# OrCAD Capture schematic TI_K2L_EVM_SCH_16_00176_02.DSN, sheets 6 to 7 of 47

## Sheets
6 PAGE24 : K2L_JTAG: size C; title: K2L EMU, K2L JTAG, EMU MIPI 60,  EMU Detect, AMC/XDS200
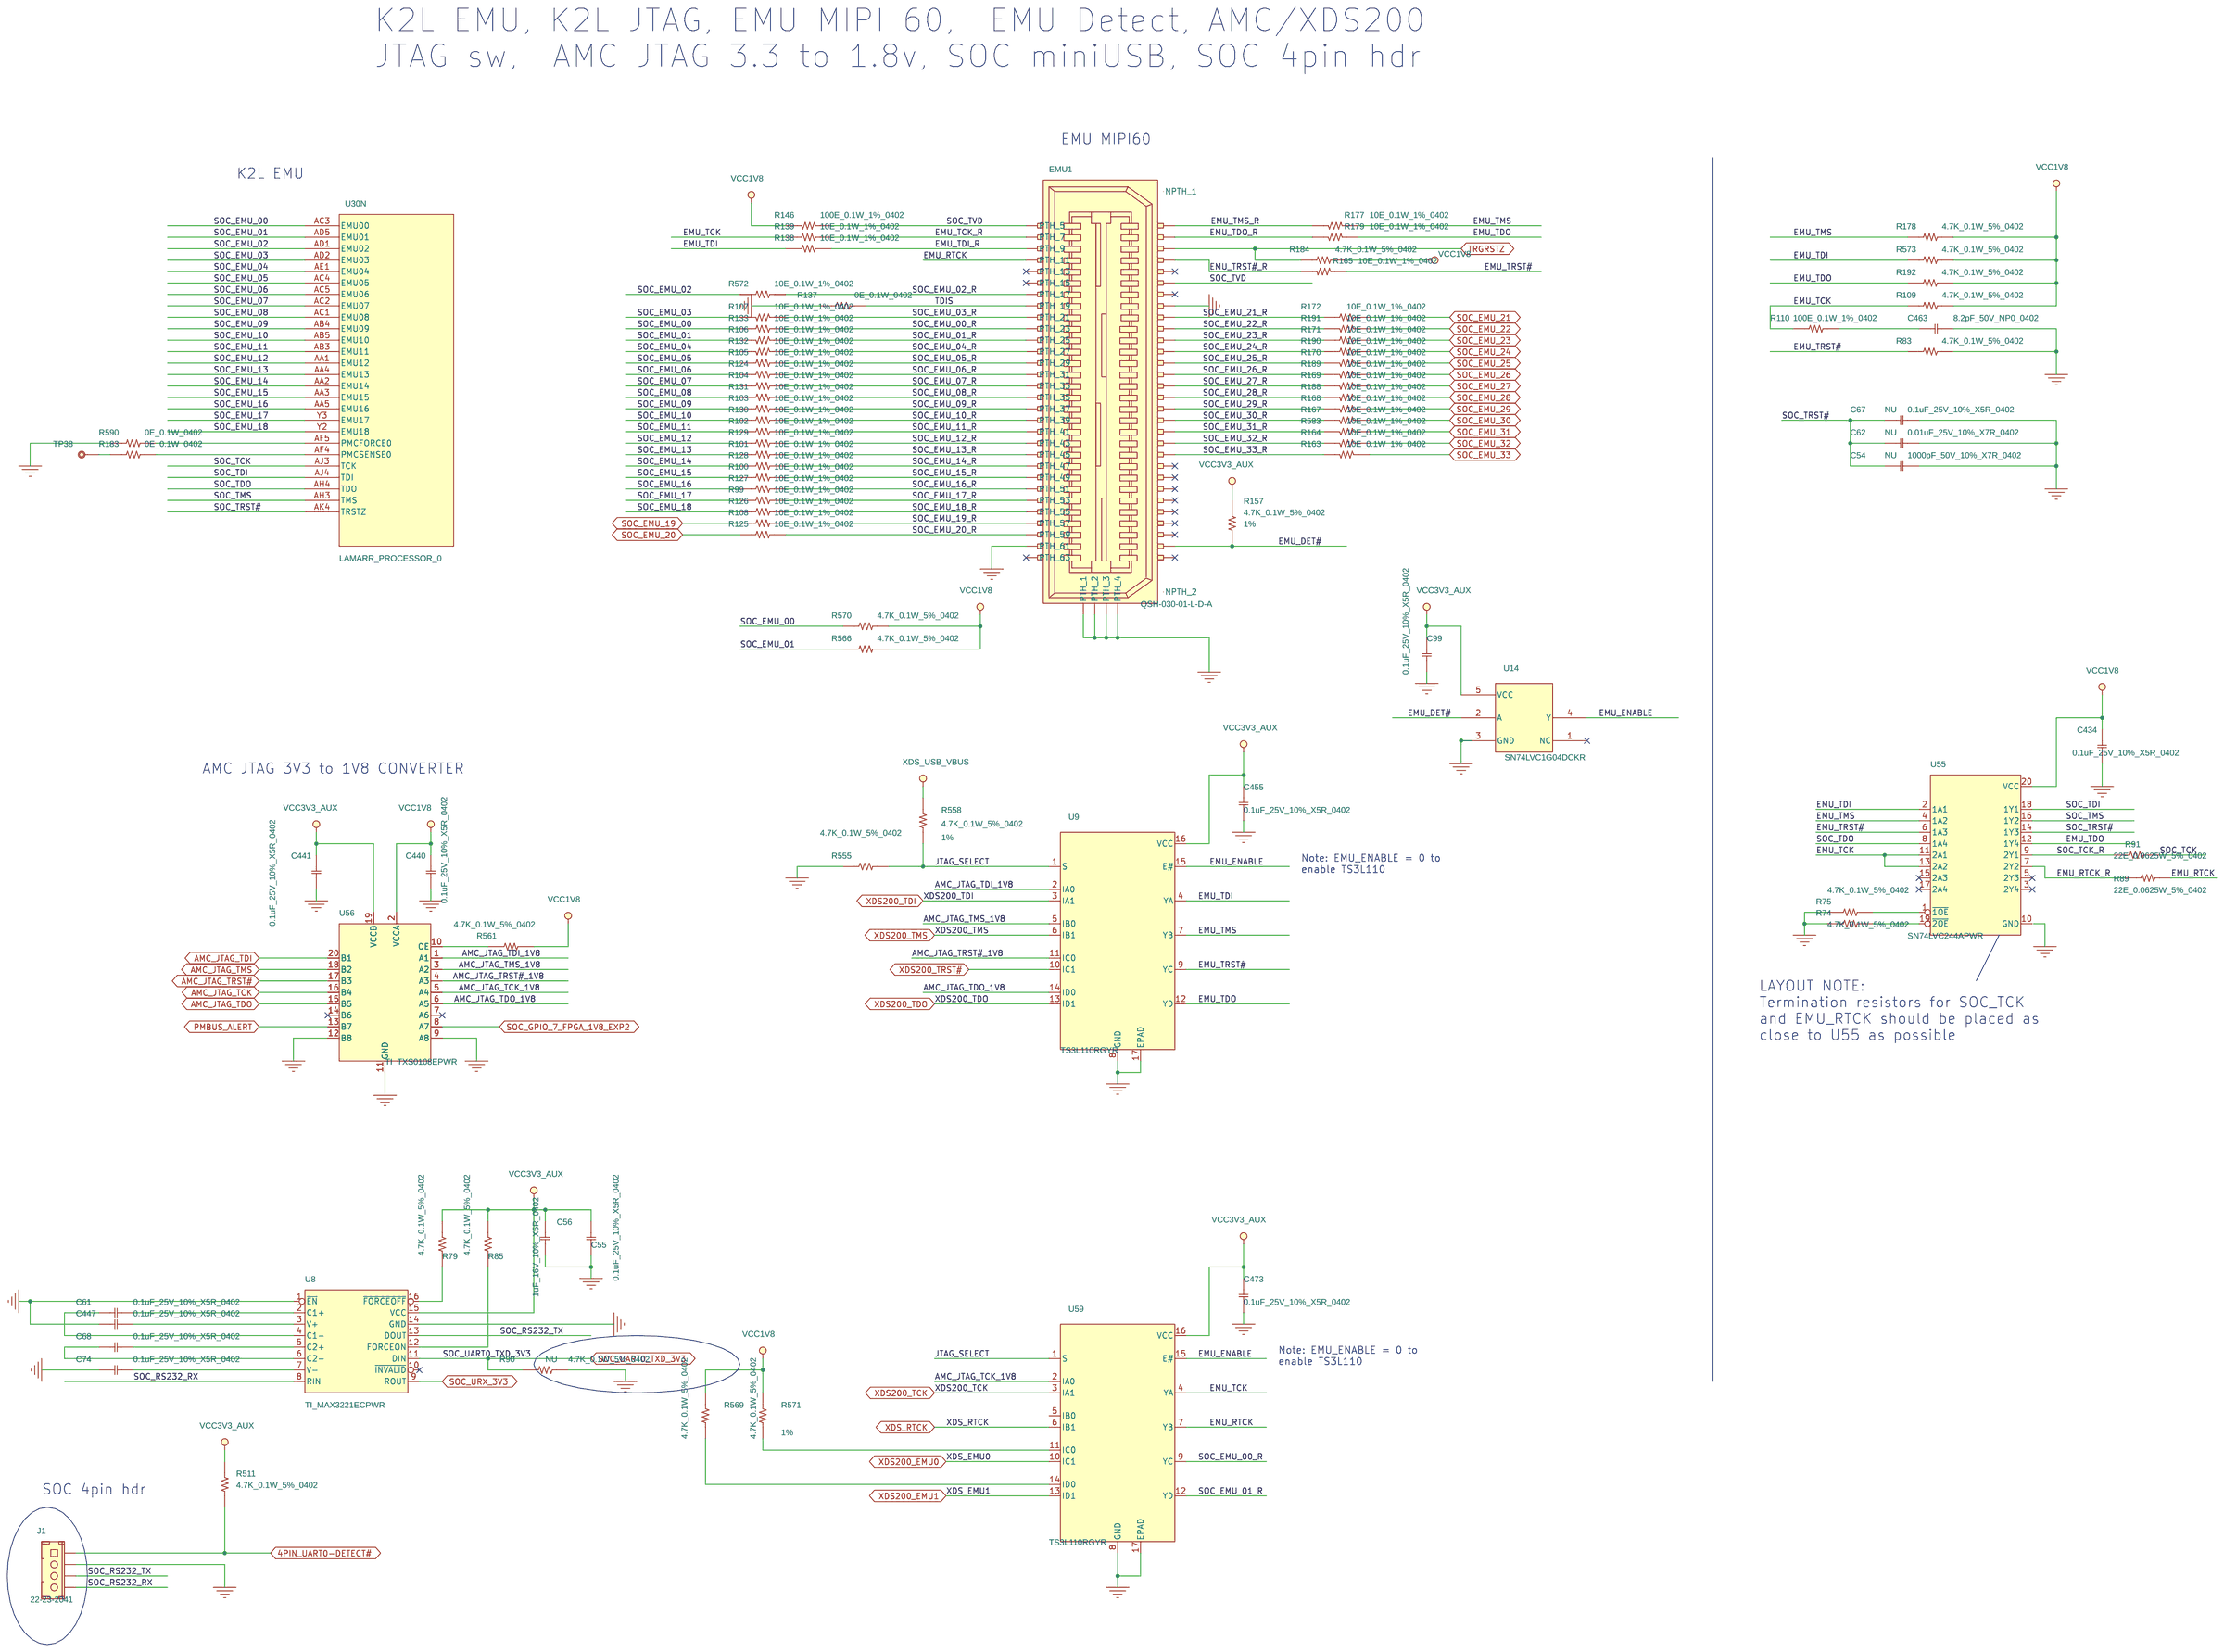
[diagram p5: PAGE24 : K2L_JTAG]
7 PAGE04 : PLACEMENT_C: title: PLACEMENT
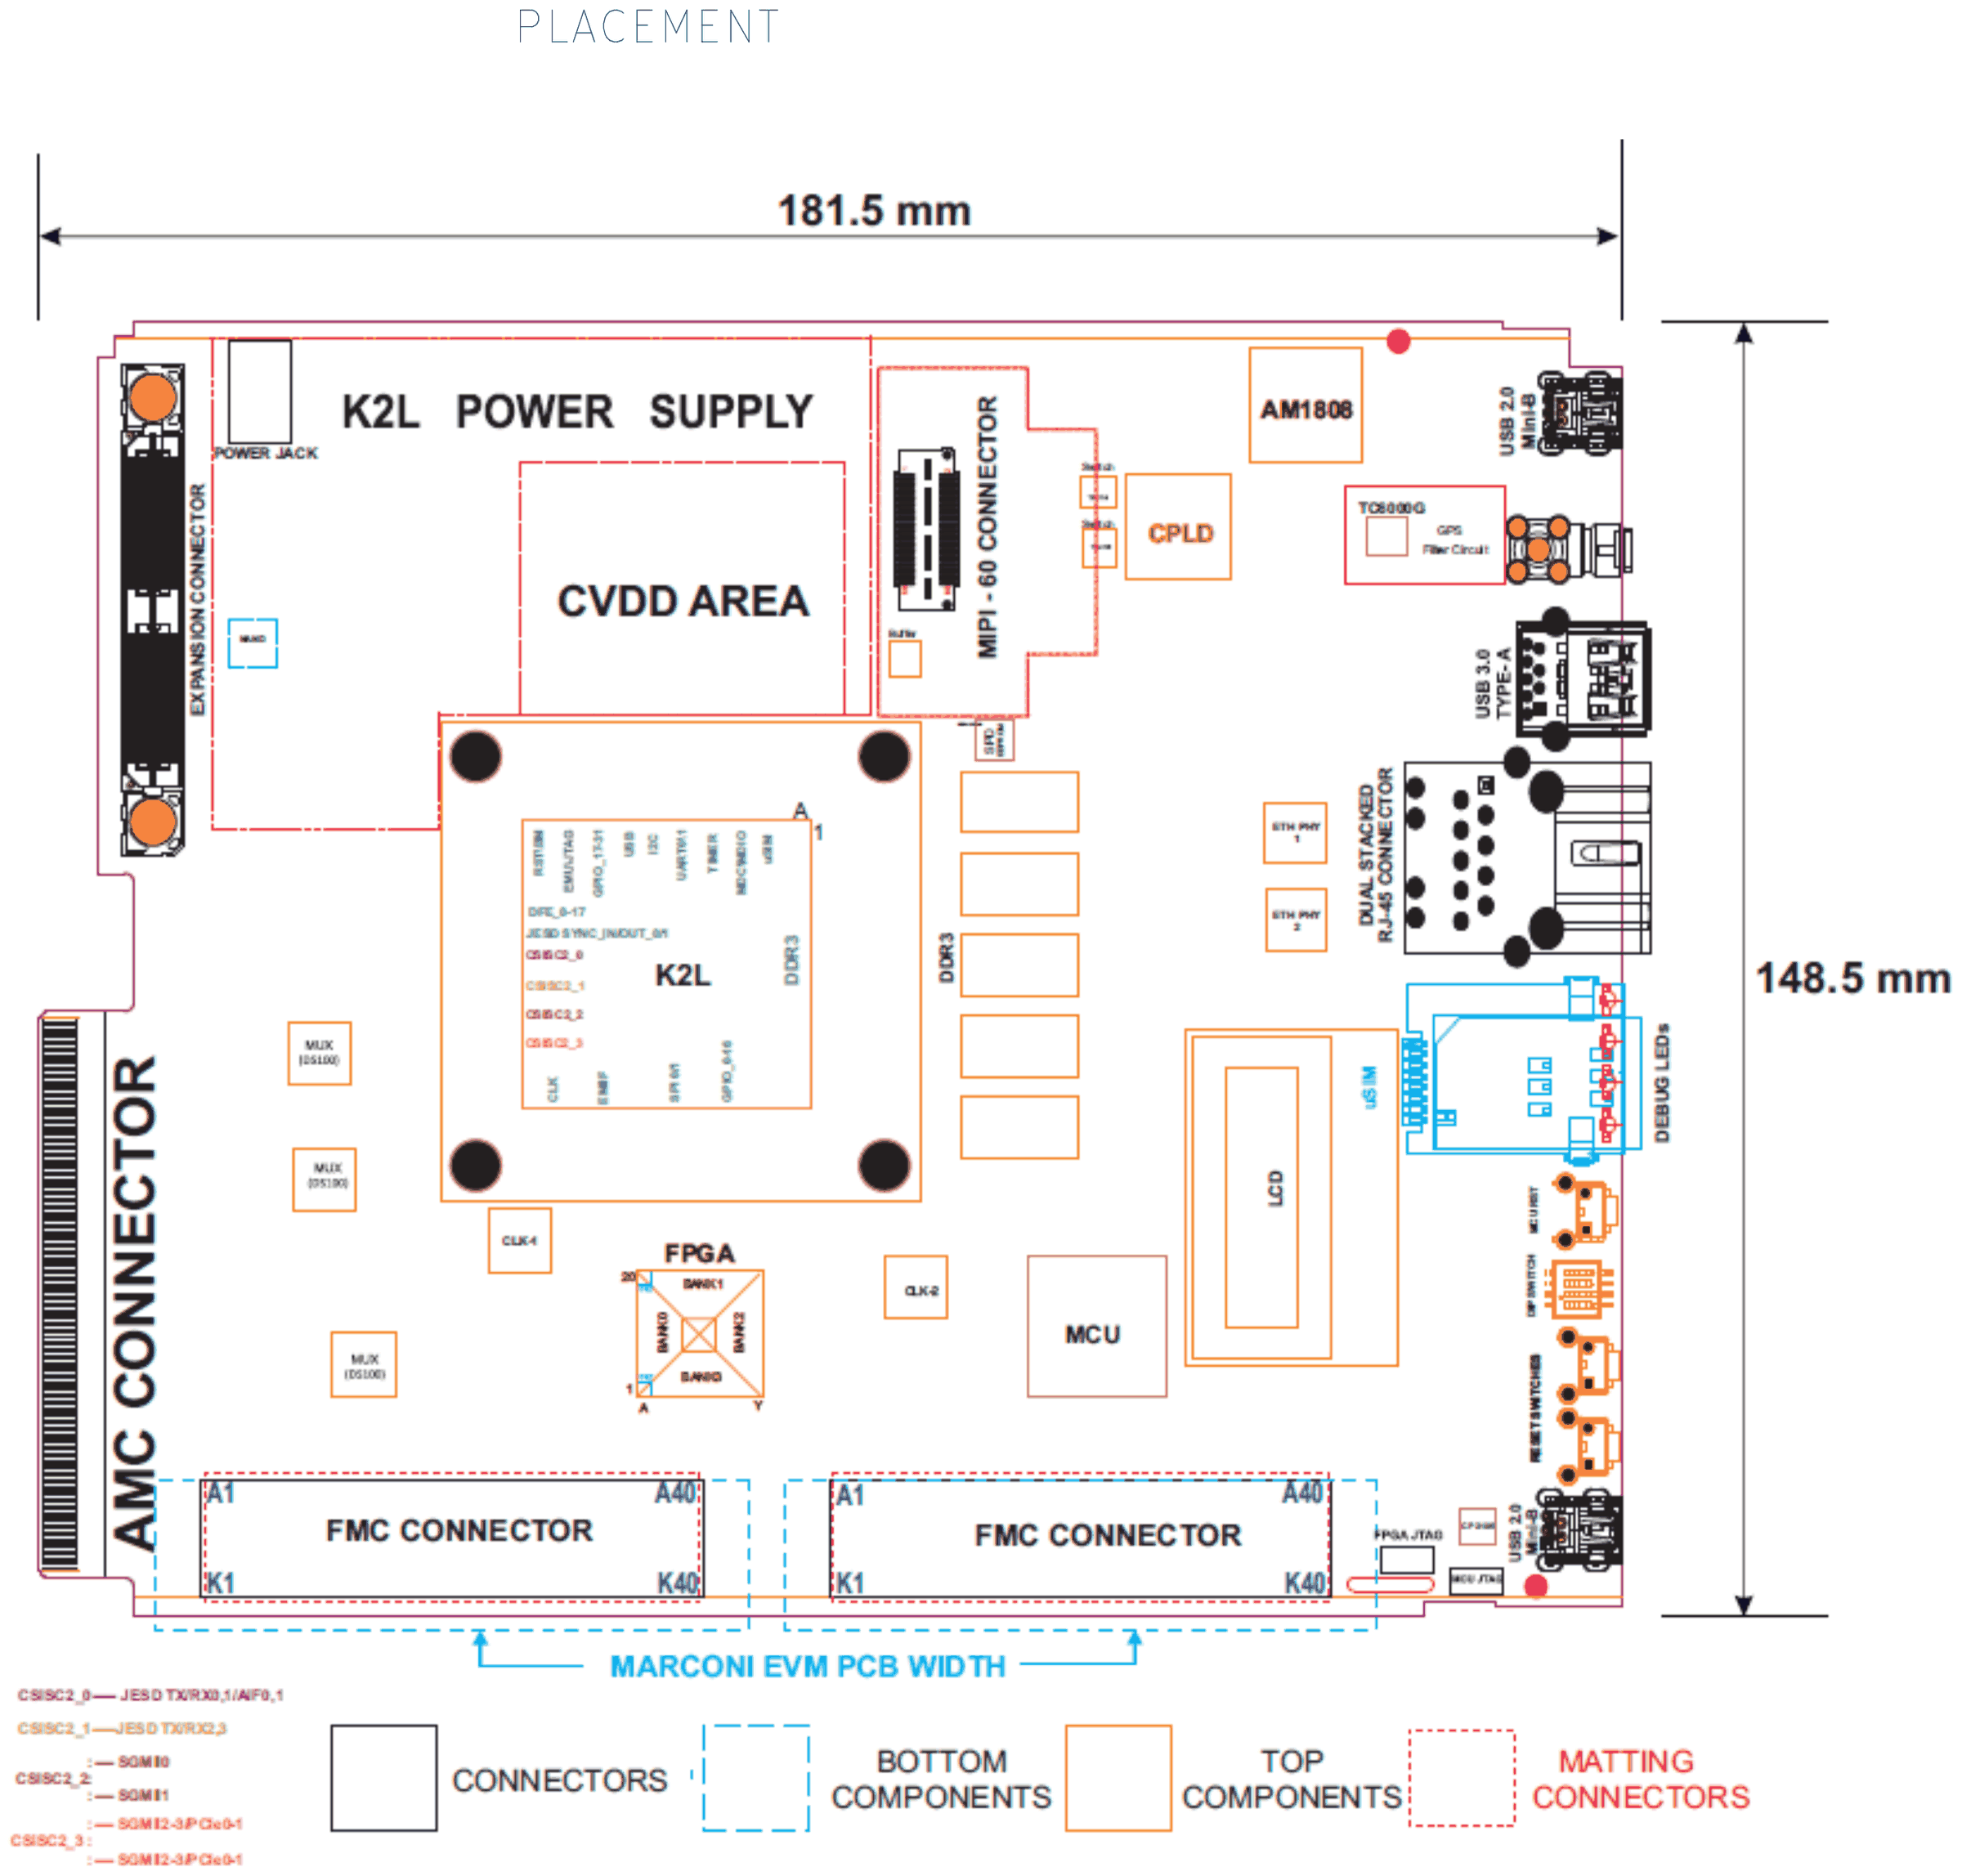
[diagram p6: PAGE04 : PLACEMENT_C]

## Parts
C54  1000pF_50V_10%_X7R_0402  [C0402]
C55  0.1uF_25V_10%_X5R_0402  [C0402]
C56  1uF_16V_10%_X5R_0402  [C0402]
C61  0.1uF_25V_10%_X5R_0402  [C0402]
C62  0.01uF_25V_10%_X7R_0402  [C0402]
C67  0.1uF_25V_10%_X5R_0402  [C0402]
C68  0.1uF_25V_10%_X5R_0402  [C0402]
C74  0.1uF_25V_10%_X5R_0402  [C0402]
C99  0.1uF_25V_10%_X5R_0402  [C0402]
C434  0.1uF_25V_10%_X5R_0402  [C0402]
C440  0.1uF_25V_10%_X5R_0402  [C0402]
C441  0.1uF_25V_10%_X5R_0402  [C0402]
C447  0.1uF_25V_10%_X5R_0402  [C0402]
C455  0.1uF_25V_10%_X5R_0402  [C0402]
C463  8.2pF_50V_NP0_0402  [C0402]
C473  0.1uF_25V_10%_X5R_0402  [C0402]
EMU1  QSH-030-01-L-D-A  [BB_30x2P_20_838x285_F]
J1  22-23-2041  [MOL22-23-2041]
R74  4.7K_0.1W_5%_0402  [R0402]
R75  4.7K_0.1W_5%_0402  [R0402]
R79  4.7K_0.1W_5%_0402  [R0402]
R83  4.7K_0.1W_5%_0402  [R0402]
R85  4.7K_0.1W_5%_0402  [R0402]
R89  22E_0.0625W_5%_0402  [R0402]
R90  4.7K_0.1W_5%_0402  [R0402]
R91  22E_0.0625W_5%_0402  [R0402]
R99  10E_0.1W_1%_0402  [R0402]
R100  10E_0.1W_1%_0402  [R0402]
R101  10E_0.1W_1%_0402  [R0402]
R102  10E_0.1W_1%_0402  [R0402]
R103  10E_0.1W_1%_0402  [R0402]
R104  10E_0.1W_1%_0402  [R0402]
R105  10E_0.1W_1%_0402  [R0402]
R106  10E_0.1W_1%_0402  [R0402]
R107  10E_0.1W_1%_0402  [R0402]
R108  10E_0.1W_1%_0402  [R0402]
R109  4.7K_0.1W_5%_0402  [R0402]
R110  100E_0.1W_1%_0402  [R0402]
R124  10E_0.1W_1%_0402  [R0402]
R125  10E_0.1W_1%_0402  [R0402]
R126  10E_0.1W_1%_0402  [R0402]
R127  10E_0.1W_1%_0402  [R0402]
R128  10E_0.1W_1%_0402  [R0402]
R129  10E_0.1W_1%_0402  [R0402]
R130  10E_0.1W_1%_0402  [R0402]
R131  10E_0.1W_1%_0402  [R0402]
R132  10E_0.1W_1%_0402  [R0402]
R133  10E_0.1W_1%_0402  [R0402]
R137  0E_0.1W_0402  [R0402]
R138  10E_0.1W_1%_0402  [R0402]
R139  10E_0.1W_1%_0402  [R0402]
R146  100E_0.1W_1%_0402  [R0402]
R157  4.7K_0.1W_5%_0402  [R0402]
R163  10E_0.1W_1%_0402  [R0402]
R164  10E_0.1W_1%_0402  [R0402]
R165  10E_0.1W_1%_0402  [R0402]
R167  10E_0.1W_1%_0402  [R0402]
R168  10E_0.1W_1%_0402  [R0402]
R169  10E_0.1W_1%_0402  [R0402]
R170  10E_0.1W_1%_0402  [R0402]
R171  10E_0.1W_1%_0402  [R0402]
R172  10E_0.1W_1%_0402  [R0402]
R177  10E_0.1W_1%_0402  [R0402]
R178  4.7K_0.1W_5%_0402  [R0402]
R179  10E_0.1W_1%_0402  [R0402]
R183  0E_0.1W_0402  [R0402]
R184  4.7K_0.1W_5%_0402  [R0402]
R188  10E_0.1W_1%_0402  [R0402]
R189  10E_0.1W_1%_0402  [R0402]
R190  10E_0.1W_1%_0402  [R0402]
R191  10E_0.1W_1%_0402  [R0402]
R192  4.7K_0.1W_5%_0402  [R0402]
R511  4.7K_0.1W_5%_0402  [R0402]
R555  4.7K_0.1W_5%_0402  [R0402]
R558  4.7K_0.1W_5%_0402  [R0402]
R561  4.7K_0.1W_5%_0402  [R0402]
R566  4.7K_0.1W_5%_0402  [R0402]
R569  4.7K_0.1W_5%_0402  [R0402]
R570  4.7K_0.1W_5%_0402  [R0402]
R571  4.7K_0.1W_5%_0402  [R0402]
R572  10E_0.1W_1%_0402  [R0402]
R573  4.7K_0.1W_5%_0402  [R0402]
R583  10E_0.1W_1%_0402  [R0402]
R590  0E_0.1W_0402  [R0402]
TP38  TP  [TP-S40]
U8  TI_MAX3221ECPWR  [SOIC_16P_26_197x252]
U9  TS3L110RGYR  [qfn50p400x350_16_pwp_ti]
U14  SN74LVC1G04DCKR  [SC70_5p]
U30  LAMARR_PROCESSOR_0  [SKTBGA_Z3566_SS900-RHFB-BGA080]  (sections A,B,C,D,E,F,G,H,I,J,K,L,M,N,O,P,Q,R,S,T,U)
U55  SN74LVC244APWR  [SOIC_20P_26_256X252]
U56  TI_TXS0108EPWR  [SOIC_20P_26_256x252]
U59  TS3L110RGYR  [qfn50p400x350_16_pwp_ti]

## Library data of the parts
C54 = 11_C_0: CAP CER 1000PF 50V 10% X7R 0402; Advansus_Part_Number: 11G232110214030; Characteristic: 50V; Distributor_name: DIGIKEY; Distributor_part_number: 1276-1493-1-ND; EIC Part#: 03_00591_01; Manufacture: Samsung; Manufacture Part Number: CL05B102KB5NFNC; Manufacture(English): Samsung; Manufacture_Part_Number: CL05B102KB5NFNC; Manufacturer: Samsung; Manufacturer_Part_No: CL05B102KB5NFNC; Mfg: Samsung; Mfg Part#: CL05B102KB5NFNC; Mfr_name: Samsung; Mfr_part_number: CL05B102KB5NFNC; Mounting Status: NU; Mounting_Status: NU; Package: 0402; Part_Number: 1124510291; Price @ 1: 0.10000; Price @ 10K: 0.00216; Price @ 1K: 0.00309; ProcessType: SMT; Tolerance: 10%; Vendor: DIGIKEY; Vendor Part#: 1276-1493-1-ND; Vendor_Part_No: 1276-1493-1-ND; eI Part#: 03_00591_01
C55 C61 C68 C74 C447 = 11_C_0: CAP CER 0.1UF 25V 10% X5R 0402; Avalue_Part_Number: E1123510400H; Distributor_name: DIGIKEY; Distributor_part_number: 445-4964-1-ND; EIC Part#: 03_00470_02; MOUNTED: <MOUNTED>; Manufacture: TDK Corporation; Manufacture Part Number: C1005X5R1E104K050BC; Manufacture(English): TDK Corporation; Manufacture_Part_Number: GRM155R71C104KA88D; Manufacturer: TDK Corporation; Manufacturer_Part_No: C1005X5R1E104K050BC; Mfg: Murata Electronics North America; Mfg Part#: 03_00470_02; Mfr_name: TDK Corporation; Mfr_part_number: C1005X5R1E104K050BC; Package: 0402; Price @ 1: 0.10000; Price @ 1K: 0.00420; ProcessType: SMT; Tolerance: 10%; Vendor: DIGIKEY; Vendor Part#: 445-4964-1-ND; Vendor_Part_No: 445-4964-1-ND; eI Part#: 03_00470_02
C56 = 11_C_0: CAP CER 1UF 16V 10% X5R 0402; Characteristic: 6.3V; Distributor_name: DIGIKEY; Distributor_part_number: 445-4978-1-ND; EIC Part#: 03_00355_04; Manufacture: TDK Corporation; Manufacture Part Number: C1005X5R1C105K050BC; Manufacture(English): TDK Corporation; Manufacture_Part_Number: C1005X5R1C105K050BC; Manufacturer: TDK Corporation; Manufacturer_Part_No: C1005X5R1C105K050BC; Mfg: TDK Corporation; Mfg Part#: C1005X5R1C105K050BC; Mfr_name: TDK Corporation; Mfr_part_number: C1005X5R1C105K050BC; Package: 0402; Part_Number: 1100000870; Price @ 1: 0.10000; Price @ 10K: 0.01155; Price @ 1K: 0.01650; ProcessType: SMT; Tolerance: 10%; Vendor: DIGIKEY; Vendor_Part_No: 445-4978-1-ND; eI Part#: 03_00355_04
C62 = 11_C_0: CAP CER 10000PF 25V 10% X7R 0402; Advansus_Part_Number: 11G232110312030; Characteristic: 16V; Distributor_name: DIGIKEY; Distributor_part_number: 445-1260-1-ND; EIC Part#: 03_00029_04; GROUP: CPU1; Manufacture: TDK Corporation; Manufacture Part Number: C1005X7R1E103K; Manufacture(English): TDK Corporation; Manufacture_Part_Number: C1005X7R1E103K; Manufacturer: TDK Corporation; Manufacturer_Part_No: C1005X7R1E103K; Mfg: TDK Corporation; Mfg Part#: 03_00029_04; Mfr_name: TDK Corporation; Mfr_part_number: C1005X7R1E103K; Mounting Status: NU; Mounting_Status: NU; Package: 0402; Part_Number: 1121610790; Price @ 1: 0.10000; Price @ 10K: 0.00420; Price @ 1K: 0.00600; ProcessType: SMT; ROOM: CPU1; Tolerance: 10%; Vendor: DIGIKEY; Vendor_Part_No: 445-1260-1-ND; eI Part#: 03_00029_04
C67 = 11_C_0: CAP CER 0.1UF 25V 10% X5R 0402; Avalue_Part_Number: E1123510400H; Distributor_name: DIGIKEY; Distributor_part_number: 445-4964-1-ND; EIC Part#: 03_00470_02; Manufacture: TDK Corporation; Manufacture Part Number: C1005X5R1E104K050BC; Manufacture(English): TDK Corporation; Manufacture_Part_Number: GRM155R71C104KA88D; Manufacturer: TDK Corporation; Manufacturer_Part_No: C1005X5R1E104K050BC; Mfg: Murata Electronics North America; Mfg Part#: 03_00470_02; Mfr_name: TDK Corporation; Mfr_part_number: C1005X5R1E104K050BC; Mounting Status: NU; Mounting_Status: NU; Package: 0402; Price @ 1: 0.10000; Price @ 1K: 0.00420; ProcessType: SMT; Tolerance: 10%; Vendor: DIGIKEY; Vendor Part#: 445-4964-1-ND; Vendor_Part_No: 445-4964-1-ND; eI Part#: 03_00470_02
C99 C434 C440 C441 C455 C473 = 11_C_12: CAP CER 0.1UF 25V 10% X5R 0402; Alt Mfg: Taiyo Yuden; Distributor_name: DIGIKEY; Distributor_part_number: 445-4964-1-ND; EIC Part#: 03_00470_02; Manufacture: TDK Corporation; Manufacture Part Number: C1005X5R1E104K050BC; Manufacture(English): TDK Corporation; Manufacture_Part_Number: GRM155R61E104KA87D; Manufacturer: TDK Corporation; Manufacturer_Part_No: C1005X5R1E104K050BC; Mfg: Murata Electronics North America; Mfg Part#: 03_00470_02; Mfr_name: TDK Corporation; Mfr_part_number: C1005X5R1E104K050BC; Oper. Temp. Range: -55°C ~ 85°C; Package: 0402; Price @ 1: 0.10000; Price @ 1K: 0.00960; ProcessType: SMT; RoHS: Yes; Tolerance: 10%; Vendor: DIGIKEY; Vendor Part#: 445-4964-1-ND; Vendor_Part_No: 445-4964-1-ND; eI Part#: 03_00470_02
C463 = 11_C_12: CAP CER 8.2PF 50V NPO 0402; Advansus_Part_Number: 11G232010004030; Characteristic: 50V; Distributor_name: DIGIKEY; Distributor_part_number: 311-1012-1-ND; EIC Part#: 03_00587_01; Manufacture: Yageo; Manufacture Part Number: CC0402DRNPO9BN8R2; Manufacture(English): Yageo; Manufacture_Part_Number: CC0402DRNPO9BN8R2; Manufacturer: Yageo; Manufacturer_Part_No: CC0402DRNPO9BN8R2; Mfg: Yageo; Mfg Part#: 03_00587_01; Mfr_name: Yageo; Mfr_part_number: CC0402DRNPO9BN8R2; Package: 0402; Part_Number: 1124410091; Price @ 1: 0.10000; Price @ 10K: 0.00993; Price @ 1K: 0.01419; ProcessType: SMT; RoHS: Yes; Tolerance: 5%; Vendor: DIGIKEY; Vendor Part#: 311-1012-1-ND; Vendor_Part_No: 311-1012-1-ND; Voltage: 50V; eI Part#: 03_00587_01
EMU1 = 1654_BB_30X2P_2HOLD_QSH_0: CONN RCPT HI-SPD .5MM 60POS DL; Distributor_name: DIGIKEY; Distributor_part_number: SAM8180-ND; EIC Part#: 09_00733_01; Manufacture: Samtec Inc; Manufacture(English): Samtec Inc; Manufacturer: Samtec Inc; Mfg: Samtec Inc; Mfg Part#: 09_00733_01; Mfr_name: Samtec Inc; Package: BB60P-S0.5; Part_Number: 1654004662; Price @ 1: 9.40000; Price @ 10K: 5.54600; Price @ 1K: 5.87500; ProcessType: SMT; Vendor: DIGIKEY; Vendor_Part_No: SAM8180-ND; eI Part#: 09_00733_01
J1 = 12_WF_4P_BOX_D_0: CONN HEADER 4POS .100 VERT TIN; AVL_Part: AVL; Advansus_Part_Number: 12G080104049; Distributor_name: DIGIKEY; Distributor_part_number: WM4202-ND; EIC Part#: 09_00060_01; Manufacture: Molex Inc; Manufacture(English): Molex Inc; Manufacturer: Molex Inc; Mfg: Molex Inc; Mfg Part#: 09_00060_01; Mfr_name: Molex Inc; Package: WB4P-2.00; Part_Number: 1655000674-01; Price @ 1: 0.37000; Price @ 10K: 0.16192; Price @ 1K: 0.17710; ProcessType: DIP; Vendor: DIGIKEY; Vendor_Part_No: WM4202-ND; eI Part#: NA
R74 R75 R157 R184 R555 R558 R561 R566 R569-R571 = 10_R_0: RES 4.7K OHM 1/10W 5% 0402 SMD; Alt Mfg: Yageo; Alt Mfg Part#: RC0402JR-074K7L; Distributor_name: DIGIKEY; Distributor_part_number: P4.7KJCT-ND; EIC Part#: 02_00023_01; Manufacture: Panasonic - ECG; Manufacture Part Number: ERJ-2GEJ472X; Manufacture(English): Panasonic - ECG; Manufacture_Part_Number: ERJ-2GEJ472X; Manufacturer: Panasonic - ECG; Manufacturer_Part_No: ERJ-2GEJ472X; Mfg Part#: 02_00023_01; Mfr_name: Panasonic - ECG; Mfr_part_number: ERJ-2GEJ472X; Oper. Temp. Range: -55C to 125C; Package: 0402; ProcessType: SMT; Remark: Alt part is 1/16W; RoHS: Yes; Tolerance: 1%; Vendor: DIGIKEY; Vendor Part#: P4.7KJCT-ND; Vendor_Part_No: P4.7KJCT-ND; eI Part#: 02_00023_01
R79 R85 R511 = 10_R_0: RES 4.7K OHM 1/10W 5% 0402 SMD; Advansus_Part_Number: 10G212472004030; Avalue_Part_Number: E1050704720H; Characteristic: 5%; Distributor_name: DIGIKEY; Distributor_part_number: P4.7KJCT-ND; EIC Part#: 02_00023_01; MOUNTED: <MOUNTED>; Manufacture: Panasonic - ECG; Manufacture Part Number: ERJ-2GEJ472X; Manufacture(English): Panasonic - ECG; Manufacture_Part_Number: ERJ-2GEJ472X; Manufacturer: Panasonic - ECG; Manufacturer_Part_No: ERJ-2GEJ472X; Mfg: Panasonic Electronic Components; Mfg Part#: 02_00266_01; Mfr_name: Panasonic - ECG; Mfr_part_number: ERJ-2GEJ472X; Package: 0402; Part_Number: 105A747014; Price @ 1: 0.10000; Price @ 10K: 0.00347; Price @ 1K: 0.00672; ProcessType: SMT; Tolerance: 5%; Vendor: DIGIKEY; Vendor_Part_No: P4.7KJCT-ND; eI Part#: 02_00023_01
R83 R109 R178 R192 R573 = 10_R_0: RES 4.7K OHM 1/10W 5% 0402 SMD; Alt Mfg: Yageo; Alt Mfg Part#: RC0402JR-074K7L; Distributor_name: DIGIKEY; Distributor_part_number: P4.7KJCT-ND; EIC Part#: 02_00023_01; Manufacture: Panasonic - ECG; Manufacture Part Number: ERJ-2GEJ472X; Manufacture(English): Panasonic - ECG; Manufacture_Part_Number: ERJ-2GEJ472X; Manufacturer: Panasonic - ECG; Manufacturer_Part_No: ERJ-2GEJ472X; Mfg Part#: 02_00023_01; Mfr_name: Panasonic - ECG; Mfr_part_number: ERJ-2GEJ472X; Oper. Temp. Range: -55C to 125C; Package: 0402; ProcessType: SMT; Remark: Alt part is 1/16W; RoHS: Yes; Vendor: DIGIKEY; Vendor Part#: P4.7KJCT-ND; Vendor_Part_No: P4.7KJCT-ND; eI Part#: 02_00023_01
R89 R91 = 10_R_0: RES 22 OHM 1/16W 1% 0402 SMD; Characteristic: 5%; Distributor_name: DIGIKEY; Distributor_part_number: P22JCT-ND; EIC Part#: 02_00233_01; Manufacture: Panasonic - ECG; Manufacture Part Number: ERJ-2GEJ220X; Manufacture(English): Panasonic - ECG; Manufacture_Part_Number: ERJ-2GEJ220X; Manufacturer: Panasonic - ECG; Manufacturer_Part_No: ERJ-2GEJ220X; Mfg: Panasonic - ECG; Mfg Part#: ERJ-2GEJ220X; Mfr_name: Panasonic - ECG; Mfr_part_number: ERJ-2GEJ220X; Oper. Temp. Range: -55C to 125C; Package: 0402; ProcessType: SMT; RoHS: Yes; Tolerance: 5%; Vendor: DIGIKEY; Vendor Part#: P22JCT-ND; Vendor_Part_No: P22JCT-ND; eI Part#: 02_00233_01
R90 = 10_R_0: RES 4.7K OHM 1/10W 5% 0402 SMD; Advansus_Part_Number: 10G212472004030; Avalue_Part_Number: E1050704720H; Characteristic: 5%; Distributor_name: DIGIKEY; Distributor_part_number: P4.7KJCT-ND; EIC Part#: 02_00023_01; MOUNTED: <MOUNTED>; Manufacture: Panasonic - ECG; Manufacture Part Number: ERJ-2GEJ472X; Manufacture(English): Panasonic - ECG; Manufacture_Part_Number: ERJ-2GEJ472X; Manufacturer: Panasonic - ECG; Manufacturer_Part_No: ERJ-2GEJ472X; Mfg: Panasonic Electronic Components; Mfg Part#: 02_00266_01; Mfr_name: Panasonic - ECG; Mfr_part_number: ERJ-2GEJ472X; Mounting Status: NU; Mounting_Status: NU; Package: 0402; Part_Number: 105A747014; Price @ 1: 0.10000; Price @ 10K: 0.00347; Price @ 1K: 0.00672; ProcessType: SMT; Tolerance: 5%; Vendor: DIGIKEY; Vendor_Part_No: P4.7KJCT-ND; eI Part#: 02_00023_01
R99 = 10_R_0: RES 10.0 OHM 1/10W 1% 0402 SMD; Characteristic: 5%; Distributor_name: DIGIKEY; Distributor_part_number: P10.0LCT-ND; EIC Part#: 02_00348_01; Manufacture: Panasonic - ECG; Manufacture Part Number: ERJ-2RKF10R0X; Manufacture(English): Panasonic - ECG; Manufacture_Part_Number: ERJ-2RKF10R0X; Manufacturer: Panasonic - ECG; Manufacturer_Part_No: ERJ-2RKF10R0X; Mfg: Panasonic Electronic Components; Mfg Part#: 02_00348_01; Mfr_name: Panasonic - ECG; Mfr_part_number: ERJ-2RKF10R0X; Oper. Temp. Range: -55C to 125C; Package: 0402; Price @ 1: 0.10000; Price @ 10K: 0.00347; Price @ 1K: 0.00672; ProcessType: SMT; RoHS: Yes; Tolerance: 1%; Vendor: DIGIKEY; Vendor Part#: P10.0LCT-ND; Vendor_Part_No: P10.0LCT-ND; eI Part#: TBD
R100 R101 = 10_R_0: RES 10.0 OHM 1/10W 1% 0402 SMD; Characteristic: 5%; Distributor_name: DIGIKEY; Distributor_part_number: P10.0LCT-ND; EIC Part#: 02_00348_01; Manufacture: Panasonic - ECG; Manufacture Part Number: ERJ-2RKF10R0X; Manufacture(English): Panasonic - ECG; Manufacture_Part_Number: ERJ-2RKF10R0X; Manufacturer: Panasonic - ECG; Manufacturer_Part_No: ERJ-2RKF10R0X; Mfg: Panasonic Electronic Components; Mfg Part#: 02_00348_01; Mfr_name: Panasonic - ECG; Mfr_part_number: ERJ-2RKF10R0X; Oper. Temp. Range: -55C to 125C; Package: 0402; Price @ 1: 0.10000; Price @ 10K: 0.00347; Price @ 1K: 0.00672; ProcessType: SMT; RoHS: Yes; Tolerance: 1%; Vendor: DIGIKEY; Vendor Part#: P10.0LCT-ND; Vendor_Part_No: P10.0LCT-ND; eI Part#: 02_00037_01
R102 R103 R105 R107 R126-R129 R131 R133 R138 R139 R165 R168-R172 R177 R179 R190 R191 R572 R583 = 10_R_0: RES 10.0 OHM 1/10W 1% 0402 SMD; Characteristic: 5%; Distributor_name: DIGIKEY; Distributor_part_number: P10.0LCT-ND; EIC Part#: 02_00348_01; Manufacture: Panasonic - ECG; Manufacture Part Number: ERJ-2RKF10R0X; Manufacture(English): Panasonic - ECG; Manufacture_Part_Number: ERJ-2RKF10R0X; Manufacturer: Panasonic - ECG; Manufacturer_Part_No: ERJ-2RKF10R0X; Mfg: Panasonic Electronic Components; Mfg Part#: 02_00348_01; Mfr_name: Panasonic - ECG; Mfr_part_number: ERJ-2RKF10R0X; Oper. Temp. Range: -55C to 125C; Package: 0402; Price @ 1: 0.10000; Price @ 10K: 0.00347; Price @ 1K: 0.00672; ProcessType: SMT; RoHS: Yes; Tolerance: 1%; Vendor: DIGIKEY; Vendor Part#: P10.0LCT-ND; Vendor_Part_No: P10.0LCT-ND; eI Part#: 02_00348_01
R104 R124 R132 = 10_R_0: RES 10.0 OHM 1/10W 1% 0402 SMD; Characteristic: 5%; Distributor_name: DIGIKEY; Distributor_part_number: P10.0LCT-ND; EIC Part#: 02_00348_01; Manufacture: Panasonic - ECG; Manufacture Part Number: ERJ-2RKF10R0X; Manufacture(English): Panasonic - ECG; Manufacture_Part_Number: ERJ-2RKF10R0X; Manufacturer: Panasonic - ECG; Manufacturer_Part_No: ERJ-2RKF10R0X; Mfg: Panasonic Electronic Components; Mfg Part#: 02_00348_01; Mfr_name: Panasonic - ECG; Mfr_part_number: ERJ-2RKF10R0X; Oper. Temp. Range: -55C to 125C; Package: 0402; Price @ 1: 0.10000; Price @ 10K: 0.00347; Price @ 1K: 0.00672; ProcessType: SMT; RoHS: Yes; Tolerance: 1%; Vendor: DIGIKEY; Vendor Part#: P10.0LCT-ND; Vendor_Part_No: P10.0LCT-ND; eI Part#: 02_00266_01
R106 = 10_R_0: RES 10.0 OHM 1/10W 1% 0402 SMD; Characteristic: 5%; Distributor_name: DIGIKEY; Distributor_part_number: P10.0LCT-ND; EIC Part#: 02_00348_01; Manufacture: Panasonic - ECG; Manufacture Part Number: ERJ-2RKF10R0X; Manufacture(English): Panasonic - ECG; Manufacture_Part_Number: ERJ-2RKF10R0X; Manufacturer: Panasonic - ECG; Manufacturer_Part_No: ERJ-2RKF10R0X; Mfg: Panasonic Electronic Components; Mfg Part#: 02_00348_01; Mfr_name: Panasonic - ECG; Mfr_part_number: ERJ-2RKF10R0X; Oper. Temp. Range: -55C to 125C; Package: 0402; Price @ 1: 0.10000; Price @ 10K: 0.00347; Price @ 1K: 0.00672; ProcessType: SMT; RoHS: Yes; Tolerance: 1%; Vendor: DIGIKEY; Vendor Part#: P10.0LCT-ND; Vendor_Part_No: P10.0LCT-ND; eI Part#: 02_00234_02
R108 R125 R130 R163 = 10_R_0: RES 10.0 OHM 1/10W 1% 0402 SMD; Characteristic: 5%; Distributor_name: DIGIKEY; Distributor_part_number: P10.0LCT-ND; EIC Part#: 02_00348_01; Manufacture: Panasonic - ECG; Manufacture Part Number: ERJ-2RKF10R0X; Manufacture(English): Panasonic - ECG; Manufacture_Part_Number: ERJ-2RKF10R0X; Manufacturer: Panasonic - ECG; Manufacturer_Part_No: ERJ-2RKF10R0X; Mfg: Panasonic Electronic Components; Mfg Part#: 02_00348_01; Mfr_name: Panasonic - ECG; Mfr_part_number: ERJ-2RKF10R0X; Oper. Temp. Range: -55C to 125C; Package: 0402; Price @ 1: 0.10000; Price @ 10K: 0.00347; Price @ 1K: 0.00672; ProcessType: SMT; RoHS: Yes; Tolerance: 1%; Vendor: DIGIKEY; Vendor Part#: P10.0LCT-ND; Vendor_Part_No: P10.0LCT-ND; eI Part#: 02_00027_01
R110 = 10_R_0: RES 100 OHM 1/10W 1% 0402 SMD; Characteristic: 1%; Distributor_name: DIGIKEY; Distributor_part_number: P100LCT-ND; EIC Part#: 02_00043_02; Manufacture: Panasonic - ECG; Manufacture Part Number: ERJ-2RKF1000X; Manufacture(English): Panasonic - ECG; Manufacture_Part_Number: ERJ-2RKF1000X; Manufacturer: Panasonic - ECG; Manufacturer_Part_No: ERJ-2RKF1000X; Mfg: Panasonic Electronic Components; Mfg Part#: 02_00043_02; Mfr_name: Panasonic - ECG; Mfr_part_number: ERJ-2RKF1000X; Package: 0402; Part_Number: 105A510004; Price @ 1: 0.10000; Price @ 10K: 0.00347; Price @ 1K: 0.00672; ProcessType: SMT; Tolerance: 1%; Vendor: DIGIKEY; Vendor_Part_No: P100LCT-ND; eI Part#: 02_00043_02
R137 R183 R590 = 10_R_0: RES 0.0 OHM 1/10W JUMP 0402 SMD; Alt Mfg: Yageo; Distributor_name: DIGIKEY; Distributor_part_number: P0.0JCT-ND; EIC Part#: 02_00019_01; Manufacture: Panasonic - ECG; Manufacture Part Number: ERJ-2GE0R00X; Manufacture(English): Panasonic - ECG; Manufacture_Part_Number: ERJ-2GE0R00X; Manufacturer: Panasonic - ECG; Manufacturer_Part_No: ERJ-2GE0R00X; Mfg Part#: 02_00019_01; Mfr_name: Panasonic - ECG; Mfr_part_number: ERJ-2GE0R00X; Oper. Temp. Range: -55C to 125C; Package: 0402; ProcessType: SMT; Remark: Alt part is 1/16W; RoHS: Yes; Tolerance: 5%; Vendor: DIGIKEY; Vendor Part#: P0.0JCT-ND; Vendor_Part_No: P0.0JCT-ND; eI Part#: 02_00019_01
R146 = 10_R_0: RES 100 OHM 1/10W 1% 0402 SMD; Characteristic: 1%; Distributor_name: DIGIKEY; Distributor_part_number: P100LCT-ND; EIC Part#: 02_00043_02; MOUNTED: <MOUNTED>; Manufacture: Panasonic - ECG; Manufacture Part Number: ERJ-2RKF1000X; Manufacture(English): Panasonic - ECG; Manufacture_Part_Number: ERJ-2RKF1000X; Manufacturer: Panasonic - ECG; Manufacturer_Part_No: ERJ-2RKF1000X; Mfg: Panasonic Electronic Components; Mfg Part#: 02_00043_02; Mfr_name: Panasonic - ECG; Mfr_part_number: ERJ-2RKF1000X; Package: 0402; Part_Number: 105A510004; Price @ 1: 0.10000; Price @ 10K: 0.00347; Price @ 1K: 0.00672; ProcessType: SMT; Tolerance: 1%; Vendor: DIGIKEY; Vendor_Part_No: P100LCT-ND; eI Part#: 02_00043_02
R164 = 10_R_0: RES 10.0 OHM 1/10W 1% 0402 SMD; Characteristic: 5%; Distributor_name: DIGIKEY; Distributor_part_number: P10.0LCT-ND; EIC Part#: 02_00348_01; Manufacture: Panasonic - ECG; Manufacture Part Number: ERJ-2RKF10R0X; Manufacture(English): Panasonic - ECG; Manufacture_Part_Number: ERJ-2RKF10R0X; Manufacturer: Panasonic - ECG; Manufacturer_Part_No: ERJ-2RKF10R0X; Mfg: Panasonic Electronic Components; Mfg Part#: 02_00348_01; Mfr_name: Panasonic - ECG; Mfr_part_number: ERJ-2RKF10R0X; Oper. Temp. Range: -55C to 125C; Package: 0402; Price @ 1: 0.10000; Price @ 10K: 0.00347; Price @ 1K: 0.00672; ProcessType: SMT; RoHS: Yes; Tolerance: 1%; Vendor: DIGIKEY; Vendor Part#: P10.0LCT-ND; Vendor_Part_No: P10.0LCT-ND; eI Part#: 02_00019_01
R167 = 10_R_0: RES 10.0 OHM 1/10W 1% 0402 SMD; Characteristic: 5%; Distributor_name: DIGIKEY; Distributor_part_number: P10.0LCT-ND; EIC Part#: 02_00348_01; Manufacture: Panasonic - ECG; Manufacture Part Number: ERJ-2RKF10R0X; Manufacture(English): Panasonic - ECG; Manufacture_Part_Number: ERJ-2RKF10R0X; Manufacturer: Panasonic - ECG; Manufacturer_Part_No: ERJ-2RKF10R0X; Mfg: Panasonic Electronic Components; Mfg Part#: 02_00348_01; Mfr_name: Panasonic - ECG; Mfr_part_number: ERJ-2RKF10R0X; Oper. Temp. Range: -55C to 125C; Package: 0402; Price @ 1: 0.10000; Price @ 10K: 0.00347; Price @ 1K: 0.00672; ProcessType: SMT; RoHS: Yes; Tolerance: 1%; Vendor: DIGIKEY; Vendor Part#: P10.0LCT-ND; Vendor_Part_No: P10.0LCT-ND; eI Part#: 02_00043_02
R188 = 10_R_0: RES 10.0 OHM 1/10W 1% 0402 SMD; Characteristic: 5%; Distributor_name: DIGIKEY; Distributor_part_number: P10.0LCT-ND; EIC Part#: 02_00348_01; Manufacture: Panasonic - ECG; Manufacture Part Number: ERJ-2RKF10R0X; Manufacture(English): Panasonic - ECG; Manufacture_Part_Number: ERJ-2RKF10R0X; Manufacturer: Panasonic - ECG; Manufacturer_Part_No: ERJ-2RKF10R0X; Mfg: Panasonic Electronic Components; Mfg Part#: 02_00348_01; Mfr_name: Panasonic - ECG; Mfr_part_number: ERJ-2RKF10R0X; Oper. Temp. Range: -55C to 125C; Package: 0402; Price @ 1: 0.10000; Price @ 10K: 0.00347; Price @ 1K: 0.00672; ProcessType: SMT; RoHS: Yes; Tolerance: 1%; Vendor: DIGIKEY; Vendor Part#: P10.0LCT-ND; Vendor_Part_No: P10.0LCT-ND; eI Part#: 02_00786_01
R189 = 10_R_0: RES 10.0 OHM 1/10W 1% 0402 SMD; Characteristic: 5%; Distributor_name: DIGIKEY; Distributor_part_number: P10.0LCT-ND; EIC Part#: 02_00348_01; Manufacture: Panasonic - ECG; Manufacture Part Number: ERJ-2RKF10R0X; Manufacture(English): Panasonic - ECG; Manufacture_Part_Number: ERJ-2RKF10R0X; Manufacturer: Panasonic - ECG; Manufacturer_Part_No: ERJ-2RKF10R0X; Mfg: Panasonic Electronic Components; Mfg Part#: 02_00348_01; Mfr_name: Panasonic - ECG; Mfr_part_number: ERJ-2RKF10R0X; Oper. Temp. Range: -55C to 125C; Package: 0402; Price @ 1: 0.10000; Price @ 10K: 0.00347; Price @ 1K: 0.00672; ProcessType: SMT; RoHS: Yes; Tolerance: 1%; Vendor: DIGIKEY; Vendor Part#: P10.0LCT-ND; Vendor_Part_No: P10.0LCT-ND; eI Part#: 02_00045_01
TP38 = 00_TP28_0: TEST PAD TP; Advansus_Part_Number: 0030000003; Avalue_Part_Number: 0030000003; Distributor_name: NA; Distributor_part_number: NA; EIC Part#: NA; Manufacture: NA; Manufacture Part Number: NA; Manufacture(English): NA; Manufacture_Part_Number: NA; Manufacturer: NA; Manufacturer_Part_No: NA; Mfg: NA; Mfg Part#: NA; Mfr_name: NA; Mfr_part_number: NA; Part_Number: 0030000003; Price @ 1: NA; Price @ 10K: NA; Price @ 1K: NA; ProcessType: SMT; Vendor: NA; Vendor_Part_No: NA; eI Part#: TBD
U8 = 141_TI_MAX3221E_0: IC RS232 3V-5.5V DRVR 16-TSSOP; Distributor_name: DIGIKEY; Distributor_part_number: 296-19825-1-ND; EIC Part#: 01_00390_01; Manufacture: TI; Manufacture Part Number: MAX3221ECPWR; Manufacture(English): TI; Manufacture_Part_Number: MAX3221ECPWR; Manufacturer: TI; Manufacturer_Part_No: MAX3221ECPWR; Mfg: TI; Mfg Part#: 01_00390_01; Mfr_name: TI; Mfr_part_number: MAX3221ECPWR; Package: TSSOP16; Part_Number: 1410020965; Price @ 1: 1.75000; Price @ 10K: 0.74250; Price @ 1K: 0.81950; ProcessType: SMT; Vendor: DIGIKEY; Vendor_Part_No: 296-19825-1-ND; eI Part#: 01_01135_01
U9 U59 = TS3L110: IC ETHERNET SWITCH QUAD 16VQFN; Distributor_name: DIGIKEY; Distributor_part_number: 296-17456-6-ND; EIC Part#: 01_01138_01; Manufacture: TI; Manufacture(English): TI; Manufacturer: TI; Mfg: TI; Mfg Part#: 01_01138_01; Mfr_name: TI; Price @ 1: 1.30000; Price @ 10K: 0.55800; Price @ 1K: 0.55800; Vendor: DIGIKEY; Vendor Part#: 296-17456-1-ND; Vendor_Part_No: 296-17456-6-ND; eI Part#: 01_01138_01
U14 = SN74LVC1G04DCKR: IC SINGLE INVERTER GATE SC70-5; Distributor_name: DIGIKEY; Distributor_part_number: 296-11600-1-ND; Manufacture: TI; Manufacture(English): TI; Manufacturer: TI; Mfg Part#: 01_00039_01; Mfr_name: TI; Price @ 1: 0.49000; Price @ 10K: 0.09000; Price @ 1K: 0.10300; Vendor: DIGIKEY; Vendor_Part_No: 296-11600-1-ND; eI Part#: 01_00039_01
U30 = LAMARR_PROCESSOR_7: LAMARR-SoC 900BGA 4DSP + 2ARM; Color: Default; Distributor_name: TBD; Distributor_part_number: TBD; EIC Part#: TBD; Location X-Coordinate: 0; Location Y-Coordinate: 0; Manufacture: TI; Manufacture Part Number: TCI6630K2L; Manufacture(English): TI; Manufacture_Part_Number: TCI6630K2L; Manufacturer: TI; Manufacturer_Part_No: TCI6630K2L; Mfg: TI; Mfg Part#: TBD; Mfr_name: TI; Mfr_part_number: LAMARR-SoC; Price @ 1: TBD; Price @ 10K: TBD; Price @ 1K: TBD; Primitive: DEFAULT; SPLIT_INST: TRUE; SWAP_INFO: (S1+S2+S3+S4+S5+S6+S7+S8+S9+S10+S11+S12+S13+S14+S15+S16+S17+S18+S19+S20+S21); Vendor: TBD; Vendor_Part_No: TBD; eI Part#: TBD
U55 = 14S_74LVC244_TSSOP20-S_1: IC BUFF/DVR 3ST OCTAL 20TSSOP; AVL_Part: AVL; Distributor_name: DIGIKEY; Distributor_part_number: 296-27784-1-ND; EIC Part#: 01_01128_01; Manufacture: TI; Manufacture Part Number: SN74LVC244APWRG3; Manufacture(English): TI; Manufacture_Part_Number: SN74LVC244APWRG3; Manufacturer: TI; Manufacturer_Part_No: SN74LVC244APWRG3; Mfg: TI; Mfg Part#: 01_01128_01; Mfr_name: TI; Mfr_part_number: SN74LVC244APWRG3; Oper. Temp. Range: -40°C ~ 125°C; Package: TSSOP20; Part_Number: 14S5A24423-01; Price @ 1: 0.49000; Price @ 10K: 0.15500; Price @ 1K: 0.17500; ProcessType: SMT; Vendor: DIGIKEY; Vendor Part#: 296-27784-2-ND; Vendor_Part_No: 296-27784-1-ND; eI Part#: 01_01128_01
U56 = 141_TI_TXS0108EPWR_0: IC 8BIT NON-INV TRANSLTR 20TSSOP; Distributor_name: DIGIKEY; Distributor_part_number: 296-23011-1-ND; EIC Part#: 01_00472_01; Manufacture: TI; Manufacture Part Number: TXS0108EPWR; Manufacture(English): TI; Manufacture_Part_Number: TXS0108EPWR; Manufacturer: TI; Manufacturer_Part_No: TXS0108EPWR; Mfg: TI; Mfg Part#: 01_00472_01; Mfr_name: TI; Mfr_part_number: TXS0108EPWR; Oper. Temp. Range: -40°C ~ 85°C; Package: TSSOP20; Part_Number: 1410020326; Price @ 1: 2.30000; Price @ 10K: 0.90000; Price @ 1K: 0.91800; ProcessType: SMT; RoHS: Yes; Vendor: DIGIKEY; Vendor Part#: 296-23011-1-ND; Vendor_Part_No: 296-23011-1-ND; eI Part#: 01_01158_01

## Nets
GND: C54.1 C55.1 C56.2 C62.2 C67.2 C74.1 C99.2 C434.2 C440.2 C441.2 C447.1 C455.2 C463.2 C473.2 EMU1.16 EMU1.57(PTH_61) EMU1.H3(PTH_1) EMU1.H4(PTH_2) EMU1.H5(PTH_3) EMU1.H6(PTH_4) J1.2 R74.1 R75.1 R83.2 R90.2 R137.1 R555.1 R590.1 U8.1(~{EN}) U8.14(GND) U9.8(GND) U9.17(EPAD) U14.3(GND) U55.10(GND) U56.9(A8) U56.11(GND) U56.12(B8) U59.8(GND) U59.17(EPAD) ; also on sheet 1 2 3 4 5 8 10 11 12 13 14 15 16 17 18 19 20 21 22 24 25 26 27 28 29 33 34 35 36 37 40 41 42 43 45 46 47
VCC1V8: C434.1 C440.1 R109.2 R146.1 R178.2 R184.2 R192.2 R561.2 R566.2 R569.2 R570.2 R571.2 R573.2 U55.20(VCC) U56.2(VCCA) ; also on sheet 2 8 11 19 21 22 25 26 27 29 33 34 36 37 41
VCC3V3_AUX: C55.2 C56.1 C99.1 C441.1 C455.1 C473.1 R79.1 R85.1 R157.2 R511.1 U8.15(VCC) U9.16(VCC) U14.5(VCC) U56.19(VCCB) U59.16(VCC) ; also on sheet 2 4 8 11 12 13 16 18 19 22 25 26 27 28 29 33 35 37 40 45 47
4PIN_UART0-DETECT#: J1.1 R511.2 ; also on sheet 8
AMC_JTAG_TCK: U56.16(B4) ; also on sheet 18
AMC_JTAG_TCK_1V8: U56.5(A4) U59.2(IA0)
AMC_JTAG_TDI: U56.20(B1) ; also on sheet 18
AMC_JTAG_TDI_1V8: U9.2(IA0) U56.1(A1)
AMC_JTAG_TDO: U56.15(B5) ; also on sheet 18
AMC_JTAG_TDO_1V8: U9.14(ID0) U56.6(A5)
AMC_JTAG_TMS: U56.18(B2) ; also on sheet 18
AMC_JTAG_TMS_1V8: U9.5(IB0) U56.3(A2)
AMC_JTAG_TRST#: U56.17(B3) ; also on sheet 18
AMC_JTAG_TRST#_1V8: U9.11(IC0) U56.4(A3)
EMU_DET#: EMU1.58 R157.1 U14.2(A)
EMU_ENABLE: U9.15(E#) U14.4(Y) U59.15(E#)
EMU_RTCK: EMU1.7(PTH_11) R89.1 U59.7(YB)
EMU_RTCK_R: R89.2 U55.7(2Y2)
EMU_TCK: R109.1 R110.2 R139.1 U55.11(2A1) U55.13(2A2) U59.4(YA)
EMU_TCK_R: EMU1.3(PTH_7) R139.2
EMU_TDI: R138.1 R573.1 U9.4(YA) U55.2(1A1)
EMU_TDI_R: EMU1.5(PTH_9) R138.2
EMU_TDO: R179.1 R192.1 U9.12(YD) U55.12(1Y4)
EMU_TDO_R: EMU1.4 R179.2
EMU_TMS: R177.1 R178.1 U9.7(YB) U55.4(1A2)
EMU_TMS_R: EMU1.2 R177.2
EMU_TRST#: R83.1 R165.1 U9.9(YC) U55.6(1A3)
EMU_TRST#_R: EMU1.8 R165.2
JTAG_SELECT: R555.2 R558.1 U9.1(S) U59.1(S)
PMBUS_ALERT: U56.13(B7) ; also on sheet 5 34 35 37
SOC_EMU_00: R133.1 R570.1 U30.AC3(EMU00)
SOC_EMU_00_R: EMU1.19(PTH_23) R133.2 U59.9(YC)
SOC_EMU_01: R106.2 R566.1 U30.AD5(EMU01)
SOC_EMU_01_R: EMU1.21(PTH_25) R106.1 U59.12(YD)
SOC_EMU_02: R572.1 U30.AD1(EMU02)
SOC_EMU_02_R: EMU1.13(PTH_17) R572.2
SOC_EMU_03: R107.2 U30.AD2(EMU03)
SOC_EMU_03_R: EMU1.17(PTH_21) R107.1
SOC_EMU_04: R132.2 U30.AE1(EMU04)
SOC_EMU_04_R: EMU1.23(PTH_27) R132.1
SOC_EMU_05: R105.1 U30.AC4(EMU05)
SOC_EMU_05_R: EMU1.25(PTH_29) R105.2
SOC_EMU_06: R124.1 U30.AC5(EMU06)
SOC_EMU_06_R: EMU1.27(PTH_31) R124.2
SOC_EMU_07: R104.1 U30.AC2(EMU07)
SOC_EMU_07_R: EMU1.29(PTH_33) R104.2
SOC_EMU_08: R131.1 U30.AC1(EMU08)
SOC_EMU_08_R: EMU1.31(PTH_35) R131.2
SOC_EMU_09: R103.1 U30.AB4(EMU09)
SOC_EMU_09_R: EMU1.33(PTH_37) R103.2
SOC_EMU_10: R130.1 U30.AB5(EMU10)
SOC_EMU_10_R: EMU1.35(PTH_39) R130.2
SOC_EMU_11: R102.1 U30.AB3(EMU11)
SOC_EMU_11_R: EMU1.37(PTH_41) R102.2
SOC_EMU_12: R129.1 U30.AA1(EMU12)
SOC_EMU_12_R: EMU1.39(PTH_43) R129.2
SOC_EMU_13: R101.1 U30.AA4(EMU13)
SOC_EMU_13_R: EMU1.41(PTH_45) R101.2
SOC_EMU_14: R128.1 U30.AA2(EMU14)
SOC_EMU_14_R: EMU1.43(PTH_47) R128.2
SOC_EMU_15: R100.1 U30.AA3(EMU15)
SOC_EMU_15_R: EMU1.45(PTH_49) R100.2
SOC_EMU_16: R127.1 U30.AA5(EMU16)
SOC_EMU_16_R: EMU1.47(PTH_51) R127.2
SOC_EMU_17: R99.1 U30.Y3(EMU17)
SOC_EMU_17_R: EMU1.49(PTH_53) R99.2
SOC_EMU_18: R126.1 U30.Y2(EMU18)
SOC_EMU_18_R: EMU1.51(PTH_55) R126.2
SOC_EMU_19: R108.1 ; also on sheet 16
SOC_EMU_19_R: EMU1.53(PTH_57) R108.2
SOC_EMU_20: R125.1 ; also on sheet 16
SOC_EMU_20_R: EMU1.55(PTH_59) R125.2
SOC_EMU_21: R172.2 ; also on sheet 16
SOC_EMU_21_R: EMU1.18 R172.1
SOC_EMU_22: R191.1 ; also on sheet 16
SOC_EMU_22_R: EMU1.20 R191.2
SOC_EMU_23: R171.2 ; also on sheet 16
SOC_EMU_23_R: EMU1.22 R171.1
SOC_EMU_24: R190.2 ; also on sheet 16
SOC_EMU_24_R: EMU1.24 R190.1
SOC_EMU_25: R170.1 ; also on sheet 16
SOC_EMU_25_R: EMU1.26 R170.2
SOC_EMU_26: R189.1 ; also on sheet 16
SOC_EMU_26_R: EMU1.28 R189.2
SOC_EMU_27: R169.1 ; also on sheet 16
SOC_EMU_27_R: EMU1.30 R169.2
SOC_EMU_28: R188.1 ; also on sheet 16
SOC_EMU_28_R: EMU1.32 R188.2
SOC_EMU_29: R168.1 ; also on sheet 16
SOC_EMU_29_R: EMU1.34 R168.2
SOC_EMU_30: R167.1 ; also on sheet 16
SOC_EMU_30_R: EMU1.36 R167.2
SOC_EMU_31: R583.1 ; also on sheet 16
SOC_EMU_31_R: EMU1.38 R583.2
SOC_EMU_32: R164.1 ; also on sheet 16
SOC_EMU_32_R: EMU1.40 R164.2
SOC_EMU_33: R163.1 ; also on sheet 16
SOC_EMU_33_R: EMU1.42 R163.2
SOC_GPIO_7_FPGA_1V8_EXP2: U56.8(A7) ; also on sheet 16 21 28
SOC_RS232_RX: J1.4 U8.8(RIN)
SOC_RS232_TX: J1.3 U8.13(DOUT)
SOC_TCK: R91.1 U30.AJ3(TCK)
SOC_TCK_R: R91.2 U55.9(2Y1)
SOC_TDI: U30.AJ4(TDI) U55.18(1Y1)
SOC_TDO: U30.AH4(TDO) U55.8(1A4)
SOC_TMS: U30.AH3(TMS) U55.16(1Y2)
SOC_TRST#: C54.2 C62.1 C67.1 U30.AK4(TRSTZ) U55.14(1Y3)
SOC_TVD: EMU1.1(PTH_5) EMU1.12 R146.2
SOC_UART0_TXD_3V3: R90.1 U8.11(DIN) ; also on sheet 5 8
SOC_URX_3V3: U8.9(ROUT) ; also on sheet 8
TDIS: EMU1.15(PTH_19) R137.2
TRGRSTZ: EMU1.6 R184.1 ; also on sheet 22 42
XDS200_EMU0: U59.10(IC1) ; also on sheet 42
XDS200_EMU1: U59.13(ID1) ; also on sheet 42
XDS200_TCK: U59.3(IA1) ; also on sheet 42
XDS200_TDI: U9.3(IA1) ; also on sheet 42
XDS200_TDO: U9.13(ID1) ; also on sheet 42
XDS200_TMS: U9.6(IB1) ; also on sheet 42
XDS200_TRST#: U9.10(IC1) ; also on sheet 42
XDS_RTCK: U59.6(IB1) ; also on sheet 42
XDS_USB_VBUS: R558.2 ; also on sheet 10 15
N17735422: C463.1 R110.1
N17736378: R75.2 U55.1(~{1OE})
N17736380: R74.2 U55.19(~{2OE})
N17737125: R561.1 U56.10(OE)
N17744768: R85.2 U8.12(FORCEON)
N17744779: C447.2 U8.3(V+)
N17744781: C68.2 U8.5(C2+)
N17744783: C68.1 U8.6(C2-)
N17744789: C61.2 U8.2(C1+)
N17744791: C61.1 U8.4(C1-)
N17744799: C74.2 U8.7(V-)
N17744803: R79.2 U8.16(~{FORCEOFF})
N19299464: R571.1 U59.11(IC0)
N19299469: R569.1 U59.14(ID0)
N19479722: R590.2 U30.AF5(PMCFORCE0)
N19479725: R183.2 U30.AF4(PMCSENSE0)
N19479728: R183.1 TP38.1

Not connected (* = marked no-connect by the designer): EMU1 9(PTH_13)* 10* 11(PTH_15)* 14* 44* 46* 48* 50* 52* 54* 56* 59(PTH_63)* 60* H1(NPTH_1) H2(NPTH_2); U8 10(~{INVALID})*; U14 1(NC)*; U55 3(2Y4)* 5(2Y3)* 15(2A3)* 17(2A4)*; U56 7(A6)* 14(B6)*; U59 5(IB0)

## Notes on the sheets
sheet 6
- K2L EMU, K2L JTAG, EMU MIPI 60,  EMU Detect, AMC/XDS200
  JTAG sw,  AMC JTAG 3.3 to 1.8v, SOC miniUSB, SOC 4pin hdr
- EMU MIPI60
- K2L EMU
- AMC JTAG 3V3 to 1V8 CONVERTER
- Note: EMU_ENABLE = 0 to
  enable TS3L110
- LAYOUT NOTE:
  Termination resistors for SOC_TCK
  and EMU_RTCK should be placed as
  close to U55 as possible
- Note: EMU_ENABLE = 0 to
  enable TS3L110
- SOC 4pin hdr
sheet 7
- PLACEMENT
